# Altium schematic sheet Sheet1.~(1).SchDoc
size A
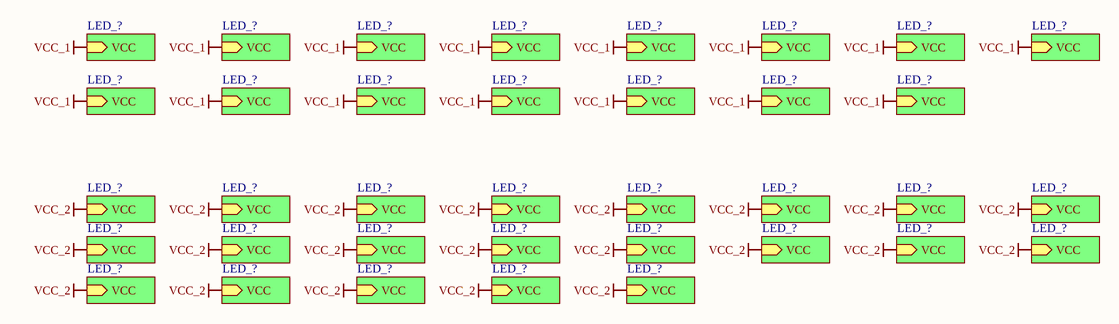
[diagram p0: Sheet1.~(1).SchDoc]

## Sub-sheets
LED_? = PCB.SchDoc: VCC
LED_? = PCB.SchDoc: VCC
LED_? = PCB.SchDoc: VCC
LED_? = PCB.SchDoc: VCC
LED_? = PCB.SchDoc: VCC
LED_? = PCB.SchDoc: VCC
LED_? = PCB.SchDoc: VCC
LED_? = PCB.SchDoc: VCC
LED_? = PCB.SchDoc: VCC
LED_? = PCB.SchDoc: VCC
LED_? = PCB.SchDoc: VCC
LED_? = PCB.SchDoc: VCC
LED_? = PCB.SchDoc: VCC
LED_? = PCB.SchDoc: VCC
LED_? = PCB.SchDoc: VCC
LED_? = PCB.SchDoc: VCC
LED_? = PCB.SchDoc: VCC
LED_? = PCB.SchDoc: VCC
LED_? = PCB.SchDoc: VCC
LED_? = PCB.SchDoc: VCC
LED_? = PCB.SchDoc: VCC
LED_? = PCB.SchDoc: VCC
LED_? = PCB.SchDoc: VCC
LED_? = PCB.SchDoc: VCC
LED_? = PCB.SchDoc: VCC
LED_? = PCB.SchDoc: VCC
LED_? = PCB.SchDoc: VCC
LED_? = PCB.SchDoc: VCC
LED_? = PCB.SchDoc: VCC
LED_? = PCB.SchDoc: VCC
LED_? = PCB.SchDoc: VCC
LED_? = PCB.SchDoc: VCC
LED_? = PCB.SchDoc: VCC
LED_? = PCB.SchDoc: VCC
LED_? = PCB.SchDoc: VCC
LED_? = PCB.SchDoc: VCC

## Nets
VCC_1: sheet LED_?/VCC, sheet LED_?/VCC, sheet LED_?/VCC, sheet LED_?/VCC, sheet LED_?/VCC, sheet LED_?/VCC, sheet LED_?/VCC, sheet LED_?/VCC, sheet LED_?/VCC, sheet LED_?/VCC, sheet LED_?/VCC, sheet LED_?/VCC, sheet LED_?/VCC, sheet LED_?/VCC, sheet LED_?/VCC
VCC_2: sheet LED_?/VCC, sheet LED_?/VCC, sheet LED_?/VCC, sheet LED_?/VCC, sheet LED_?/VCC, sheet LED_?/VCC, sheet LED_?/VCC, sheet LED_?/VCC, sheet LED_?/VCC, sheet LED_?/VCC, sheet LED_?/VCC, sheet LED_?/VCC, sheet LED_?/VCC, sheet LED_?/VCC, sheet LED_?/VCC, sheet LED_?/VCC, sheet LED_?/VCC, sheet LED_?/VCC, sheet LED_?/VCC, sheet LED_?/VCC, sheet LED_?/VCC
